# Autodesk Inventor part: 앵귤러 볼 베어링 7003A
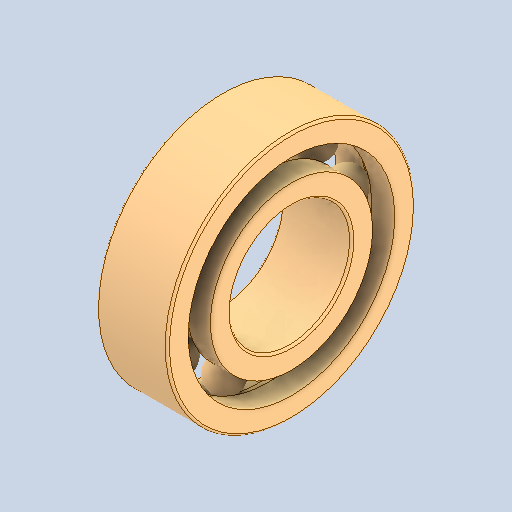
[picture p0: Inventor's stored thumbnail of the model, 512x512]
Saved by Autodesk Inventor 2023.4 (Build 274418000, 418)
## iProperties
Created: 2024-11
Part Number: 앵귤러 볼 베어링 7003A
Material: 강철, 연강
Description: 앵귤러 콘택트 볼 베어링
Document SubType Name: Modeling
Designer: EDU
Density: 7.85 g/cm^3
Appearance: 기본값
Author: jhkim
Sending System: Autodesk Inventor 2025
Preprocessor: ST-DEVELOPER v20
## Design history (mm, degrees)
feature "Solid1"
feature "Solid1:1"
feature "Solid1:2"
feature "Solid1:3"
feature "Solid1:4"
feature "Solid1:5"
feature "Solid1:6"
feature "Solid1:7"
feature "Solid1:8"
feature "Solid1:9"
feature "Solid1:10"
node "솔리드1"
node "솔리드2"
node "솔리드3"
node "솔리드4"
node "솔리드5"
node "솔리드6"
node "솔리드7"
node "솔리드8"
node "솔리드9"
node "솔리드10"
node "솔리드11"
